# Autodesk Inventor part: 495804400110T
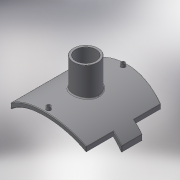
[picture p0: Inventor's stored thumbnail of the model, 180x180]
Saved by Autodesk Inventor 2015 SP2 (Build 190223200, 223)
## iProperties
Created: 2017-10
Part Number: 495804400110T
Material: Generic
Description: PLASSON BRANCH SADDLE 250-400X110
Document SubType Name: Modeling
Designer: KIM
Density: 1 g/cm^3
Appearance: Default
Author: KIM
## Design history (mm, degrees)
derived "495804 (SECOND).ipt"
feature "Solid1::495804 (SECOND).ipt"
tag "TaggingFeature1"
body "Solid1"
other parameters: "d1" = 15, "d2" = 274.5, "d4" = 0, "d5" = 305, "d6" = 75, "d7" = 0, "d8" = 135, "d10" = 0, "d11" = 2, "d12" = 225.6, "d13" = 14, "d14" = 135, "d16" = 5 deg, "d18" = 4, "d19" = 14, "d20" = 0, "d21" = 3, "d22" = 0, "d23" = 319, "d25" = 16, "d26" = 88, "d28" = 0, "d29" = 9.6, "d31" = 0, "d32" = 31.2, "d33" = 0, "d34" = 4, "d35" = 0.8, "B_" = 305, "H_" = 104, "x_" = 15, "D_" = 16
